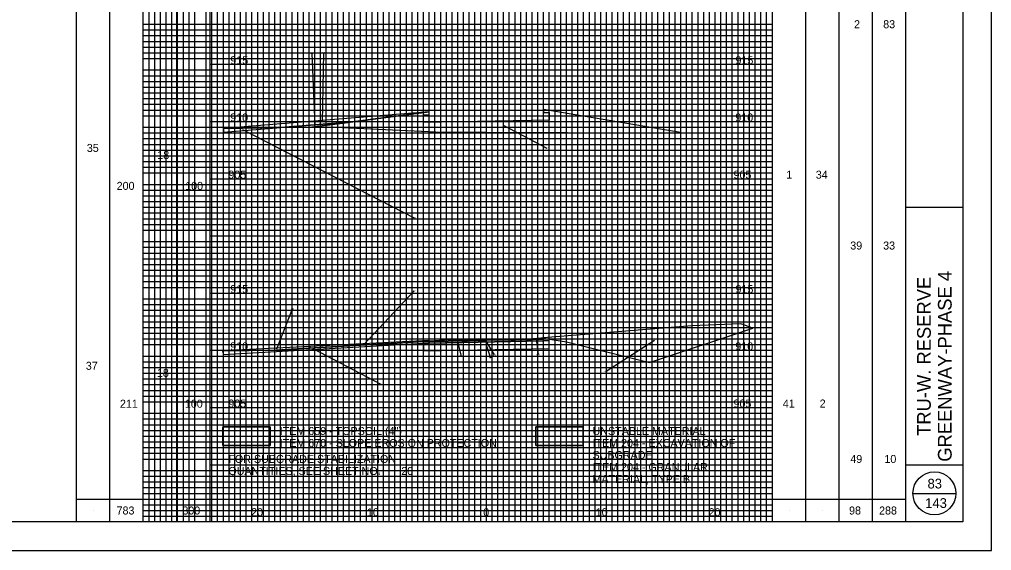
# Model space of a CAD drawing. Extents: x -73 to 160, y -2 to 1877.
# Drawn here: x 75 to 160, y 1032.5 to 1078.9 of the extents above; entities that cross this region are included whole.
import ezdxf

# ---------------------------------------------------------------- set-up
doc = ezdxf.new("R2010")
doc.units = 0
for name, color, linetype in [('DR_P_Flood_Boundary', 7, 'Continuous'), ('GK_Cells', 7, 'Continuous'), ('PV_P_Drive', 7, 'Continuous'), ('PV_P_EOP', 7, 'Continuous'), ('RD_X_Fence', 7, 'Continuous'), ('TX_X_5', 7, 'Continuous'), ('UT_P_Water_Cells', 7, 'Continuous'), ('XS_P_Pavt_Layers', 7, 'Continuous'), ('XS_P_Pavt_Surface', 7, 'Continuous'), ('XS_P_Special_Benching', 7, 'Continuous'), ('XS_X_Ground_Line', 7, 'Continuous')]:
    doc.layers.add(name, color=color, linetype=linetype)

msp = doc.modelspace()

# ---------------------------------------------------------------- linework, layer by layer
at = {"layer": 'DR_P_Flood_Boundary'}
for p, q in [((95.832, 1035), (95.832, 1140)), ((100.832, 1035), (100.832, 1140)), ((105.832, 1035), (105.832, 1140)), ((110.832, 1035), (110.832, 1140)), ((115.832, 1035), (115.832, 1140)), ((120.832, 1035), (120.832, 1140)), ((125.832, 1035), (125.832, 1140)), ((130.832, 1035), (130.832, 1140)), ((135.832, 1035), (135.832, 1140)), ((91.665, 1075), (140.832, 1075)), ((91.665, 1070), (140.832, 1070)), ((91.665, 1065), (140.832, 1065)), ((91.665, 1060), (140.832, 1060)), ((91.665, 1055), (140.832, 1055)), ((91.665, 1050), (140.832, 1050)), ((91.665, 1045), (140.832, 1045)), ((91.665, 1040), (140.832, 1040))]:
    msp.add_line(p, q, dxfattribs=at)
at = {"layer": 'GK_Cells'}
for p, q in [((152.5, 1035), (152.5, 1140)), ((152.5, 1062.5), (157.5, 1062.5)), ((152.5, 1040), (157.5, 1040))]:
    msp.add_line(p, q, dxfattribs=at)
msp.add_lwpolyline([(0, 1140), (157.5, 1140), (157.5, 1035), (0, 1035)], close=True, dxfattribs=at)
at = {"layer": 'PV_P_Drive'}
msp.add_lwpolyline([(92.792, 1043.31), (96.933, 1043.31), (96.933, 1041.695), (92.792, 1041.695)], close=True, dxfattribs=at)
msp.add_lwpolyline([(92.792, 1041.695), (96.933, 1041.695), (96.933, 1043.31), (92.792, 1043.31), (92.792, 1041.695)], dxfattribs=at)
at = {"layer": 'PV_P_EOP'}
msp.add_lwpolyline([(120.141, 1043.31), (124.282, 1043.31), (124.282, 1041.695), (120.141, 1041.695)], close=True, dxfattribs=at)
msp.add_lwpolyline([(120.141, 1041.695), (124.282, 1041.695), (124.282, 1043.31), (120.141, 1043.31), (120.141, 1041.695)], dxfattribs=at)
at = {"layer": 'RD_X_Fence'}
for p, q in [((100.859, 1069.64), (100.604, 1075.976)), ((101.486, 1069.941), (101.617, 1076.006)), ((132.807, 1069.038), (120.832, 1071.034)), ((110.832, 1070.834), (92.832, 1069.382)), ((110.832, 1070.834), (100.563, 1069.498)), ((104.149, 1069.965), (110.832, 1070.834)), ((110.332, 1070.574), (110.832, 1070.584)), ((110.332, 1069.907), (110.332, 1070.574)), ((120.832, 1070.784), (121.332, 1070.794)), ((121.332, 1070.794), (121.332, 1070.127)), ((92.832, 1069.052), (97.863, 1069.458)), ((97.863, 1069.458), (92.832, 1069.382)), ((92.832, 1069.382), (97.863, 1069.458)), ((92.832, 1069.382), (92.832, 1069.052)), ((97.863, 1069.458), (104.149, 1069.965)), ((104.149, 1069.965), (97.863, 1069.458)), ((97.863, 1069.458), (100.563, 1069.498)), ((100.563, 1069.498), (104.149, 1069.965)), ((121.332, 1070.127), (110.332, 1069.907)), ((117.289, 1069.67), (121.121, 1067.653)), ((94.509, 1069.297), (109.521, 1061.59)), ((105.099, 1050.521), (109.514, 1055.194)), ((97.514, 1050.125), (98.889, 1053.625)), ((139.115, 1051.924), (138.086, 1052.3)), ((130.102, 1048.92), (139.115, 1051.924)), ((92.832, 1049.623), (110.332, 1050.611)), ((110.832, 1050.871), (100.399, 1050.34)), ((110.832, 1050.621), (110.332, 1050.611)), ((110.332, 1050.611), (110.832, 1050.621)), ((110.332, 1050.611), (110.332, 1049.944)), ((110.832, 1050.791), (110.832, 1050.871)), ((115.833, 1050.867), (110.832, 1050.767)), ((110.832, 1050.767), (115.833, 1050.867)), ((110.832, 1050.621), (120.832, 1050.821)), ((110.832, 1050.803), (110.832, 1050.767)), ((110.832, 1050.767), (110.832, 1050.621)), ((110.832, 1050.621), (110.832, 1050.767)), ((112.982, 1050.914), (112.612, 1050.906)), ((113.473, 1050.924), (112.982, 1050.914)), ((113.275, 1050.857), (113.636, 1049.502)), ((115.832, 1050.903), (113.473, 1050.924)), ((115.781, 1050.791), (116.522, 1049.611)), ((117.089, 1050.892), (115.833, 1050.867)), ((120.597, 1051.066), (118.905, 1050.928)), ((120.832, 1050.967), (118.905, 1050.928)), ((118.905, 1050.928), (120.832, 1050.967)), ((120.181, 1050.992), (120.346, 1049.627)), ((120.832, 1051.071), (120.597, 1051.066)), ((120.832, 1050.967), (120.832, 1051.071)), ((120.832, 1051.071), (122.832, 1050.737)), ((120.832, 1050.821), (120.832, 1050.967)), ((121.332, 1050.164), (121.332, 1050.831)), ((122.832, 1050.737), (130.102, 1048.92)), ((130.522, 1050.858), (126.288, 1048.134)), ((100.388, 1050.34), (92.759, 1049.952)), ((92.759, 1049.952), (92.832, 1049.623)), ((100.399, 1050.34), (100.391, 1050.278)), ((100.396, 1050.192), (100.642, 1050.207)), ((100.645, 1050.154), (106.594, 1047.027)), ((104.19, 1050.41), (102.833, 1050.332)), ((110.332, 1049.944), (121.332, 1050.164)), ((115.832, 1050.387), (116.178, 1049.331))]:
    msp.add_line(p, q, dxfattribs=at)
for points in [[(120.832, 1071.034), (120.832, 1070.929), (120.832, 1070.784)], [(110.832, 1070.584), (110.832, 1070.729), (110.832, 1070.834)], [(100.563, 1069.498), (101.955, 1069.519), (111.406, 1069.092), (115.832, 1069.07), (130.03, 1069.002), (132.799, 1068.992)], [(132.799, 1068.992), (132.807, 1069.038)], [(138.086, 1052.3), (133.781, 1052.142), (120.831, 1051.085)], [(100.642, 1050.207), (102.833, 1050.332), (104.19, 1050.41), (108.014, 1050.629), (110.831, 1050.791), (110.832, 1050.791)], [(110.832, 1050.767), (108.014, 1050.615), (104.19, 1050.41)], [(112.612, 1050.906), (110.836, 1050.803), (110.832, 1050.803)], [(121.332, 1050.831), (120.832, 1050.821), (110.832, 1050.621)], [(115.833, 1050.867), (115.832, 1050.903)], [(118.905, 1050.928), (118.326, 1050.881), (117.089, 1050.892)], [(120.831, 1051.085), (120.832, 1051.071)], [(102.833, 1050.332), (97.45, 1050.024), (92.759, 1049.952)], [(92.759, 1049.952), (97.45, 1050.024), (100.396, 1050.192)], [(100.396, 1050.192), (100.391, 1050.278), (100.388, 1050.34)], [(100.391, 1050.278), (100.396, 1050.192)]]:
    msp.add_lwpolyline(points, dxfattribs=at)
at = {"layer": 'TX_X_5'}
msp.add_lwpolyline([(-10, 1032.5), (160, 1032.5), (160, 1142.5), (-10, 1142.5)], close=True, dxfattribs=at)
at = {"layer": 'UT_P_Water_Cells'}
for p, q in [((86.332, 1035), (86.332, 1140)), ((86.832, 1035), (86.832, 1140)), ((87.332, 1035), (87.332, 1140)), ((87.832, 1035), (87.832, 1140)), ((88.332, 1035), (88.332, 1140)), ((88.832, 1035), (88.832, 1140)), ((89.332, 1035), (89.332, 1140)), ((89.832, 1035), (89.832, 1140)), ((90.332, 1035), (90.332, 1140)), ((91.332, 1035), (91.332, 1140)), ((91.832, 1035), (91.832, 1140)), ((92.332, 1035), (92.332, 1140)), ((92.832, 1035), (92.832, 1140)), ((93.332, 1035), (93.332, 1140)), ((93.832, 1035), (93.832, 1140)), ((94.332, 1035), (94.332, 1140)), ((94.832, 1035), (94.832, 1140)), ((95.332, 1035), (95.332, 1140)), ((96.332, 1035), (96.332, 1140)), ((96.832, 1035), (96.832, 1140)), ((97.332, 1035), (97.332, 1140)), ((97.832, 1035), (97.832, 1140)), ((98.332, 1035), (98.332, 1140)), ((98.832, 1035), (98.832, 1140)), ((99.332, 1035), (99.332, 1140)), ((99.832, 1035), (99.832, 1140)), ((100.332, 1035), (100.332, 1140)), ((101.332, 1035), (101.332, 1140)), ((101.832, 1035), (101.832, 1140)), ((102.332, 1035), (102.332, 1140)), ((102.832, 1035), (102.832, 1140)), ((103.332, 1035), (103.332, 1140)), ((103.832, 1035), (103.832, 1140)), ((104.332, 1035), (104.332, 1140)), ((104.832, 1035), (104.832, 1140)), ((105.332, 1035), (105.332, 1140)), ((106.332, 1035), (106.332, 1140)), ((106.832, 1035), (106.832, 1140)), ((107.332, 1035), (107.332, 1140)), ((107.832, 1035), (107.832, 1140)), ((108.332, 1035), (108.332, 1140)), ((108.832, 1035), (108.832, 1140)), ((109.332, 1035), (109.332, 1140)), ((109.832, 1035), (109.832, 1140)), ((110.332, 1035), (110.332, 1140)), ((111.332, 1035), (111.332, 1140)), ((111.832, 1035), (111.832, 1140)), ((112.332, 1035), (112.332, 1140)), ((112.832, 1035), (112.832, 1140)), ((113.332, 1035), (113.332, 1140)), ((113.832, 1035), (113.832, 1140)), ((114.332, 1035), (114.332, 1140)), ((114.832, 1035), (114.832, 1140)), ((115.332, 1035), (115.332, 1140)), ((116.332, 1035), (116.332, 1140)), ((116.832, 1035), (116.832, 1140)), ((117.332, 1035), (117.332, 1140)), ((117.832, 1035), (117.832, 1140)), ((118.332, 1035), (118.332, 1140)), ((118.832, 1035), (118.832, 1140)), ((119.332, 1035), (119.332, 1140)), ((119.832, 1035), (119.832, 1140)), ((120.332, 1035), (120.332, 1140)), ((121.332, 1035), (121.332, 1140)), ((121.832, 1035), (121.832, 1140)), ((122.332, 1035), (122.332, 1140)), ((122.832, 1035), (122.832, 1140)), ((123.332, 1035), (123.332, 1140)), ((123.832, 1035), (123.832, 1140)), ((124.332, 1035), (124.332, 1140)), ((124.832, 1035), (124.832, 1140)), ((125.332, 1035), (125.332, 1140)), ((126.332, 1035), (126.332, 1140)), ((126.832, 1035), (126.832, 1140)), ((127.332, 1035), (127.332, 1140)), ((127.832, 1035), (127.832, 1140)), ((128.332, 1035), (128.332, 1140)), ((128.832, 1035), (128.832, 1140)), ((129.332, 1035), (129.332, 1140)), ((129.832, 1035), (129.832, 1140)), ((130.332, 1035), (130.332, 1140)), ((131.332, 1035), (131.332, 1140)), ((131.832, 1035), (131.832, 1140)), ((132.332, 1035), (132.332, 1140)), ((132.832, 1035), (132.832, 1140)), ((133.332, 1035), (133.332, 1140)), ((133.832, 1035), (133.832, 1140)), ((134.332, 1035), (134.332, 1140)), ((134.832, 1035), (134.832, 1140)), ((135.332, 1035), (135.332, 1140)), ((136.332, 1035), (136.332, 1140)), ((136.832, 1035), (136.832, 1140)), ((137.332, 1035), (137.332, 1140)), ((137.832, 1035), (137.832, 1140)), ((138.332, 1035), (138.332, 1140)), ((138.832, 1035), (138.832, 1140)), ((139.332, 1035), (139.332, 1140)), ((139.832, 1035), (139.832, 1140)), ((140.332, 1035), (140.332, 1140)), ((85.832, 1078.5), (140.832, 1078.5)), ((85.832, 1078), (140.832, 1078)), ((85.832, 1077.5), (140.832, 1077.5)), ((85.832, 1077), (140.832, 1077)), ((85.832, 1076.5), (140.832, 1076.5)), ((85.832, 1076), (140.832, 1076)), ((85.832, 1075.5), (140.832, 1075.5)), ((85.832, 1074.5), (140.832, 1074.5)), ((85.832, 1074), (140.832, 1074)), ((85.832, 1073.5), (140.832, 1073.5)), ((85.832, 1073), (140.832, 1073)), ((85.832, 1072.5), (140.832, 1072.5)), ((85.832, 1072), (140.832, 1072)), ((85.832, 1071.5), (140.832, 1071.5)), ((85.832, 1071), (140.832, 1071)), ((85.832, 1070.5), (140.832, 1070.5)), ((85.832, 1069.5), (140.832, 1069.5)), ((85.832, 1069), (140.832, 1069)), ((85.832, 1068.5), (140.832, 1068.5)), ((85.832, 1068), (140.832, 1068)), ((85.832, 1067.5), (140.832, 1067.5)), ((85.832, 1067), (140.832, 1067)), ((85.832, 1066.5), (140.832, 1066.5)), ((85.832, 1066), (140.832, 1066)), ((85.832, 1065.5), (140.832, 1065.5)), ((85.832, 1064.5), (140.832, 1064.5)), ((85.832, 1064), (140.832, 1064)), ((85.832, 1063.5), (140.832, 1063.5)), ((85.832, 1063), (140.832, 1063)), ((85.832, 1062.5), (140.832, 1062.5)), ((85.832, 1062), (140.832, 1062)), ((85.832, 1061.5), (140.832, 1061.5)), ((85.832, 1061), (140.832, 1061)), ((85.832, 1060.5), (140.832, 1060.5)), ((85.832, 1059.5), (140.832, 1059.5)), ((85.832, 1059), (140.832, 1059)), ((85.832, 1058.5), (140.832, 1058.5)), ((85.832, 1058), (140.832, 1058)), ((85.832, 1057.5), (140.832, 1057.5)), ((85.832, 1057), (140.832, 1057)), ((85.832, 1056.5), (140.832, 1056.5)), ((85.832, 1056), (140.832, 1056)), ((85.832, 1055.5), (140.832, 1055.5)), ((85.832, 1054.5), (140.832, 1054.5)), ((85.832, 1054), (140.832, 1054)), ((85.832, 1053.5), (140.832, 1053.5)), ((85.832, 1053), (140.832, 1053)), ((85.832, 1052.5), (140.832, 1052.5)), ((85.832, 1052), (140.832, 1052)), ((85.832, 1051.5), (140.832, 1051.5)), ((85.832, 1051), (140.832, 1051)), ((85.832, 1050.5), (140.832, 1050.5)), ((85.832, 1049.5), (140.832, 1049.5)), ((85.832, 1049), (140.832, 1049)), ((85.832, 1048.5), (140.832, 1048.5)), ((85.832, 1048), (140.832, 1048)), ((85.832, 1047.5), (140.832, 1047.5)), ((85.832, 1047), (140.832, 1047)), ((85.832, 1046.5), (140.832, 1046.5)), ((85.832, 1046), (140.832, 1046)), ((85.832, 1045.5), (140.832, 1045.5)), ((85.832, 1044.5), (140.832, 1044.5)), ((85.832, 1044), (140.832, 1044)), ((85.832, 1043.5), (140.832, 1043.5)), ((85.832, 1043), (140.832, 1043)), ((85.832, 1042.5), (140.832, 1042.5)), ((85.832, 1042), (140.832, 1042)), ((85.832, 1041.5), (140.832, 1041.5)), ((85.832, 1041), (140.832, 1041)), ((85.832, 1040.5), (140.832, 1040.5)), ((85.832, 1039.5), (140.832, 1039.5)), ((85.832, 1039), (140.832, 1039)), ((85.832, 1038.5), (140.832, 1038.5)), ((85.832, 1038), (140.832, 1038)), ((85.832, 1037.5), (140.832, 1037.5)), ((85.832, 1037), (140.832, 1037)), ((85.832, 1036.5), (140.832, 1036.5)), ((85.832, 1036), (140.832, 1036)), ((85.832, 1035.5), (140.832, 1035.5))]:
    msp.add_line(p, q, dxfattribs=at)
at = {"layer": 'XS_X_Ground_Line'}
for p, q in [((80, 1035), (80, 1140)), ((85.832, 1035), (85.832, 1140)), ((85.832, 1035), (85.832, 1140)), ((91.665, 1035), (91.665, 1140)), ((140.832, 1035), (140.832, 1140)), ((146.667, 1035), (146.667, 1140)), ((82.916, 1035), (82.916, 1138.75)), ((143.75, 1035), (143.75, 1138.75)), ((149.583, 1035), (149.583, 1138.75)), ((88.749, 1035), (88.749, 1136.667)), ((155, 1051.458), (155, 1051.458)), ((155, 1037.925), (155, 1037.925)), ((80, 1037), (91.665, 1037)), ((140.832, 1037), (152.5, 1037)), ((153.125, 1037.5), (156.875, 1037.5)), ((155, 1036.225), (155, 1036.225)), ((81.458, 1036.03), (81.458, 1036.03)), ((84.374, 1036.03), (84.374, 1036.03)), ((142.291, 1036), (142.291, 1036)), ((145.209, 1036), (145.209, 1036)), ((148.125, 1036), (148.125, 1036)), ((151.042, 1036), (151.042, 1036))]:
    msp.add_line(p, q, dxfattribs=at)
msp.add_circle((155, 1037.5), 1.875, dxfattribs=at)

# ---------------------------------------------------------------- texts
at = {"layer": 'RD_X_Fence'}
for s, p in [('0.6', (100.438, 1075.906)), ('4.0', (101.455, 1075.936)), ('29.4', (120.914, 1067.583)), ('0.8', (109.358, 1061.52)), ('1.2', (109.384, 1055.124)), ('0.9', (98.724, 1053.555)), ('0.4', (113.483, 1049.432)), ('7.3', (116.033, 1049.261)), ('1.4', (116.404, 1049.541)), ('0.1', (120.219, 1049.557)), ('28.3', (126.083, 1048.064)), ('3.0', (106.431, 1046.957)), ('11.9', (106.145, 1039.225))]:
    msp.add_text(s, height=0.14, dxfattribs=at).set_placement(p)
at = {"layer": 'XS_P_Pavt_Layers'}
for s, p in [('83', (154.401, 1037.925)), ('143', (154.197, 1036.225))]:
    msp.add_text(s, height=0.85, dxfattribs=at).set_placement(p)
at = {"layer": 'XS_P_Pavt_Surface'}
for s, p in [('2', (147.977, 1078.149)), ('83', (150.526, 1078.149)), ('915', (93.441, 1075)), ('915', (137.609, 1075)), ('910', (93.43, 1070)), ('910', (137.598, 1070)), ('35', (80.893, 1067.337)), ('18', (87.052, 1066.718)), ('905', (93.27, 1065)), ('905', (137.438, 1065)), ('1', (142.057, 1065)), ('34', (144.631, 1065)), ('200', (83.5, 1064.02)), ('100', (89.494, 1064.02)), ('39', (147.646, 1058.806)), ('33', (150.521, 1058.806)), ('915', (93.441, 1055)), ('915', (137.609, 1055)), ('910', (93.43, 1050)), ('910', (137.598, 1050)), ('37', (80.803, 1048.298)), ('18', (87.021, 1047.679)), ('211', (83.787, 1044.981)), ('100', (89.462, 1044.981)), ('905', (93.27, 1045)), ('905', (137.438, 1045)), ('41', (141.751, 1045)), ('2', (144.97, 1045)), ('49', (147.649, 1040.153)), ('10', (150.631, 1040.153)), ('783', (83.493, 1035.65)), ('300', (89.249, 1035.65)), ('20', (95.257, 1035.5)), ('10', (105.389, 1035.5)), ('0', (115.554, 1035.5)), ('0', (115.554, 1035.5)), ('10', (125.389, 1035.5)), ('20', (135.257, 1035.5)), ('98', (147.541, 1035.65)), ('288', (150.165, 1035.65))]:
    msp.add_text(s, height=0.7, dxfattribs=at).set_placement(p)
for s, p in [('GREENWAY-PHASE 4', (156.512, 1040.261)), ('TRU-W. RESERVE', (154.688, 1042.519))]:
    msp.add_text(s, height=1.2, rotation=90, dxfattribs=at).set_placement(p)
at = {"layer": 'XS_P_Special_Benching'}
for s, p in [('ITEM 659 - TOPSOIL (4")', (97.76, 1042.596)), ('UNSTABLE MATERIAL', (125.11, 1042.596)), ('ITEM 670 - SLOPE EROSION PROTECTION', (97.76, 1041.546)), ('ITEM 204 - EXCAVATION OF', (125.11, 1041.546)), ('FOR SUBGRADE STABILIZATION', (93.268, 1040.155)), ('SUBGRADE', (125.11, 1040.496)), ('QUANTITIES, SEE SHEET NO.', (93.268, 1039.105)), ('20', (108.386, 1039.105)), ('ITEM 204 - GRANULAR', (125.11, 1039.446)), ('MATERIAL, TYPE B', (125.11, 1038.396))]:
    msp.add_text(s, height=0.7, dxfattribs=at).set_placement(p)
at = {"layer": 'XS_X_Ground_Line'}
msp.add_text('143', height=0.85, dxfattribs=at).set_placement((154.197, 1036.225))

doc.saveas('drawing.dxf')
